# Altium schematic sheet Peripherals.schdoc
size 297 x 209 mm; Symbol: Drawing-Symbol_A4; @Project Name: Hưhwwuey; @Page Count: 2; @Update Date: 2026-10-03; @Create Date: 2026-10-03; @Schematic Name: Schematic1; @Page No: 2; @Page Name: P1; Company: EasyEDA.com; Version: V1.0; Page Size: A4; Device: Drawing-Symbol_A4; @Create Time: 22:16:09; @Update Time: 22:16:09; Border: 1; Width: 1170; Height: 825; Region Start: 1; X Region Count: 6; Y Region Count: 4; Blade Width: 10; Title Block Position: 3; @Board Name: Board1
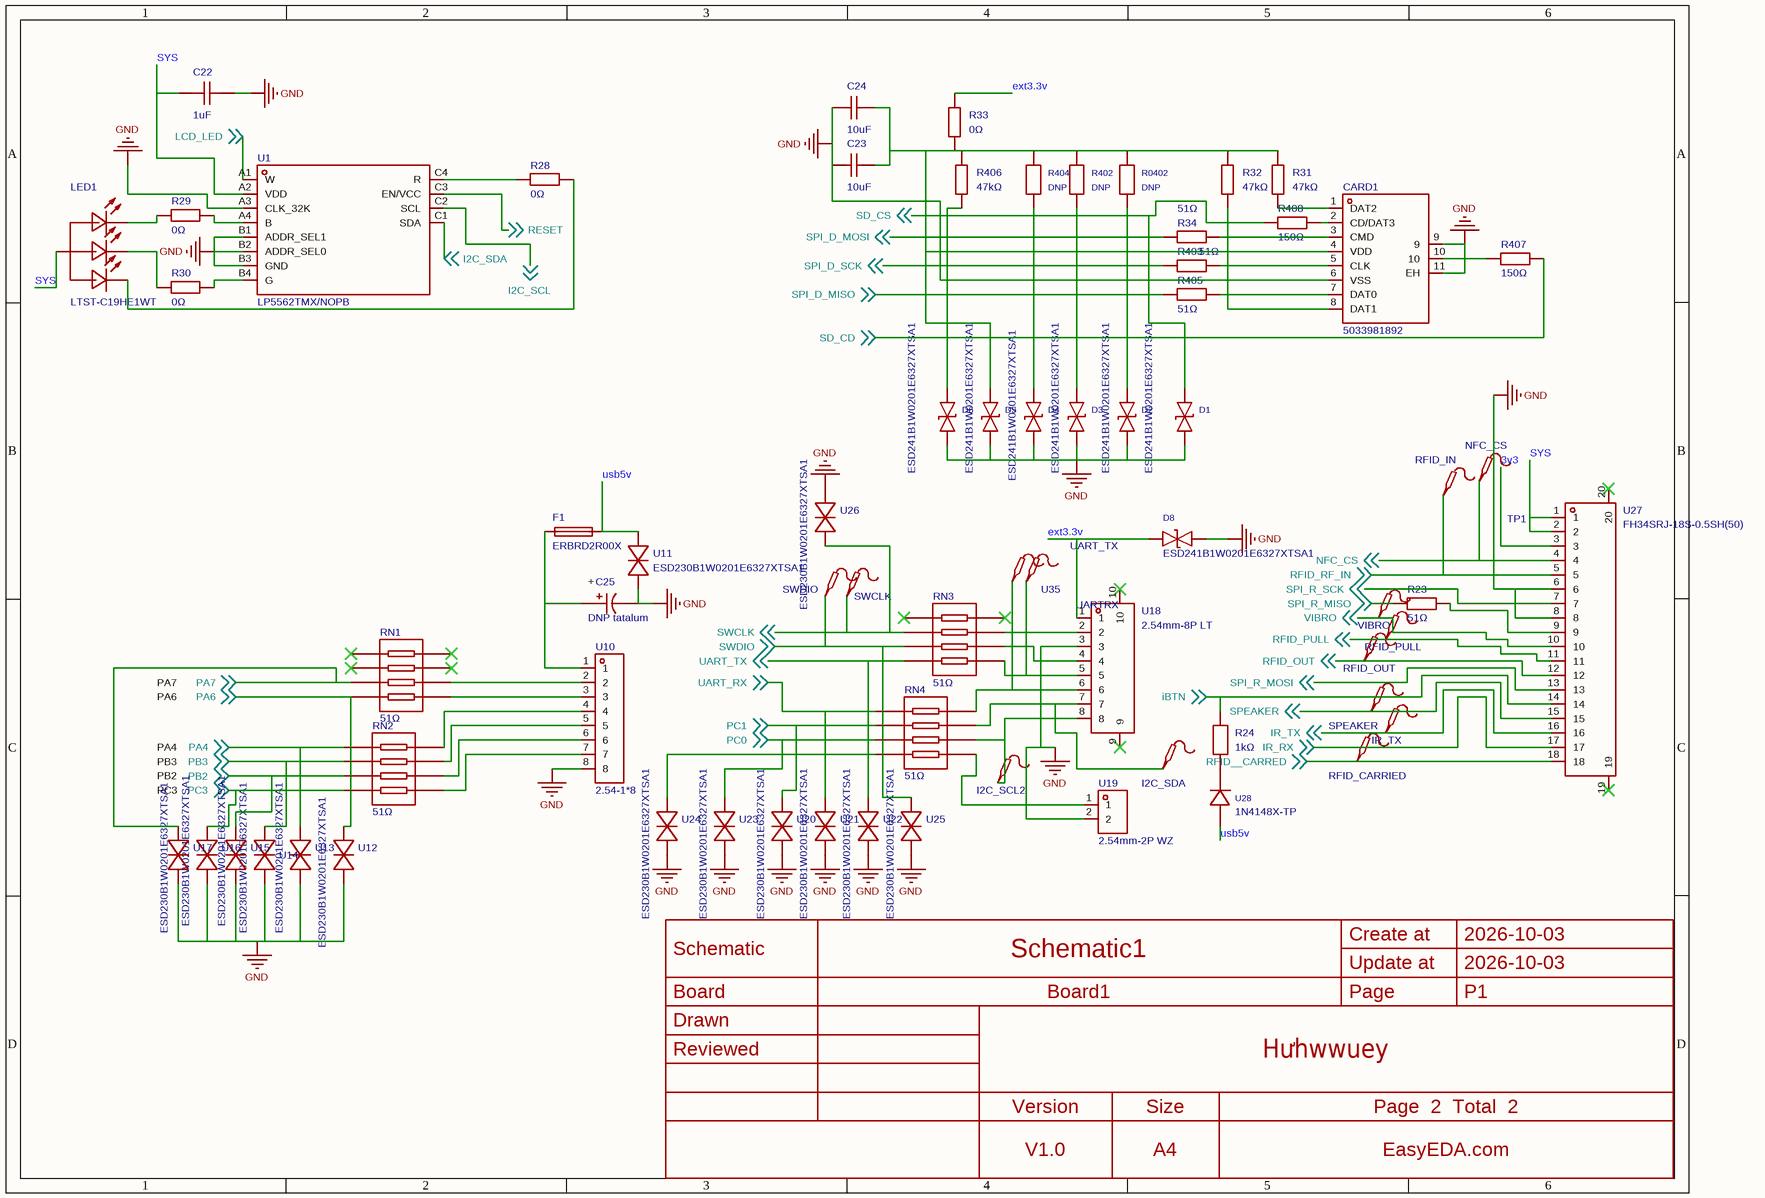
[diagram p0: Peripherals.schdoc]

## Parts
C22  1uF  [C0402]
C23  10uF  [C0603]
C24  10uF  [C0603]
C25  DNP tatalum  [CAP-TH_BD13.0-P5.00-D0.6-FD]
CARD1  5033981892  [TF-SMD_503398-1892]
D1  ESD241B1W0201E6327XTSA1  [WLL-2-3_L0.6-W0.3-P0.36-BI]
D2  ESD241B1W0201E6327XTSA1  [WLL-2-3_L0.6-W0.3-P0.36-BI]
D3  ESD241B1W0201E6327XTSA1  [WLL-2-3_L0.6-W0.3-P0.36-BI]
D4  ESD241B1W0201E6327XTSA1  [WLL-2-3_L0.6-W0.3-P0.36-BI]
D5  ESD241B1W0201E6327XTSA1  [WLL-2-3_L0.6-W0.3-P0.36-BI]
D6  ESD241B1W0201E6327XTSA1  [WLL-2-3_L0.6-W0.3-P0.36-BI]
D8  ESD241B1W0201E6327XTSA1  [WLL-2-3_L0.6-W0.3-P0.36-BI]
F1  ERBRD2R00X  [F0402]
I2C_SCL2  (no value)  [Test-Point-0.5mm]
I2C_SDA  (no value)  [Test-Point-0.5mm]
IR_TX  (no value)  [Test-Point-0.5mm]
LED1  LTST-C19HE1WT  [LED-ARRAY-SMD_4P-L1.6-W1.6-TL-CW]
NFC_CS  (no value)  [Test-Point-0.5mm]
R23  51Ω  [R0402]
R24  1kΩ  [R0402]
R28  0Ω  [R0402]
R29  0Ω  [R0402]
R30  0Ω  [R0402]
R31  47kΩ  [R0402]
R32  47kΩ  [R0402]
R33  0Ω  [R0402]
R34  51Ω  [R0402]
R0402  DNP  [R0402]
R402  DNP  [R0402]
R403  51Ω  [R0402]
R404  DNP  [R0402]
R405  51Ω  [R0402]
R406  47kΩ  [R0402]
R407  150Ω  [R0402]
R408  150Ω  [R0402]
RFID_PULL  (no value)  [Test-Point-0.5mm]
RN1  51Ω  [RES-ARRAY-SMD_0402-8P-L2.0-W1.0-BL]
RN2  51Ω  [RES-ARRAY-SMD_0402-8P-L2.0-W1.0-BL]
RN3  51Ω  [RES-ARRAY-SMD_0402-8P-L2.0-W1.0-BL]
RN4  51Ω  [RES-ARRAY-SMD_0402-8P-L2.0-W1.0-BL]
SWCLK  (no value)  [Test-Point-0.5mm]
SWDIO  (no value)  [Test-Point-0.5mm]
TP1  RFID_IN  [Test-Point-0.5mm]
TP2  RFID_OUT  [Test-Point-0.5mm]
TP3  SPEAKER  [Test-Point-0.5mm]
TP4  RFID_CARRIED  [Test-Point-0.5mm]
U1  LP5562TMX/NOPB  [DSBGA-12_L1.7-W1.3-R3-C4-P0.40-TL]
U10  2.54-1*8  [HDR-TH_8P-P2.54-V-M]
U11  ESD230B1W0201E6327XTSA1  [WLL-2-1_L0.6-W0.3-BI]
U12  ESD230B1W0201E6327XTSA1  [WLL-2-1_L0.6-W0.3-BI]
U13  ESD230B1W0201E6327XTSA1  [WLL-2-1_L0.6-W0.3-BI]
U14  ESD230B1W0201E6327XTSA1  [WLL-2-1_L0.6-W0.3-BI]
U15  ESD230B1W0201E6327XTSA1  [WLL-2-1_L0.6-W0.3-BI]
U16  ESD230B1W0201E6327XTSA1  [WLL-2-1_L0.6-W0.3-BI]
U17  ESD230B1W0201E6327XTSA1  [WLL-2-1_L0.6-W0.3-BI]
U18  2.54mm-8P LT  [CONN-SMD_8P-P2.50_SHOUHAN_2.54MM-8PLT]
U19  2.54mm-2P WZ  [CONN-TH_2P-P2.50_HX-2.54MM-2P-WZ-1]
U20  ESD230B1W0201E6327XTSA1  [WLL-2-1_L0.6-W0.3-BI]
U21  ESD230B1W0201E6327XTSA1  [WLL-2-1_L0.6-W0.3-BI]
U22  ESD230B1W0201E6327XTSA1  [WLL-2-1_L0.6-W0.3-BI]
U23  ESD230B1W0201E6327XTSA1  [WLL-2-1_L0.6-W0.3-BI]
U24  ESD230B1W0201E6327XTSA1  [WLL-2-1_L0.6-W0.3-BI]
U25  ESD230B1W0201E6327XTSA1  [WLL-2-1_L0.6-W0.3-BI]
U26  ESD230B1W0201E6327XTSA1  [WLL-2-1_L0.6-W0.3-BI]
U27  FH34SRJ-18S-0.5SH(50)  [FFC-SMD_18P-P0.50_FH34SRJ-18S-0.5SH]
U28  1N4148X-TP  [SOD-523F_L1.2-W0.8-LS1.7-RD]
U35  UART_TX  [Test-Point-0.5mm]
UARTRX  (no value)  [Test-Point-0.5mm]
VIBRO  (no value)  [Test-Point-0.5mm]

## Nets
GND: C22.2 C23.1 C24.1 C25.2 CARD1.6(VSS) CARD1.9 CARD1.11(EH) D1.1 D2.1 D3.1 D4.1 D5.1 D6.1 D8.1 U1.A3(CLK_32K) U1.B1(ADDR_SEL1) U1.B2(ADDR_SEL0) U1.B3(GND) U10.8 U11.1(C) U12.1(C) U13.1(C) U14.1(C) U15.1(C) U16.1(C) U17.1(C) U18.3 U19.2 U20.1(C) U21.1(C) U22.1(C) U23.1(C) U24.1(C) U25.1(C) U26.2(A) U27.6 U27.8
3v3: U27.3
ext3.3v: D8.2 R33.2 U18.1
I2C_SCL: U1.C2(SCL) ; off-sheet I2C_SCL
I2C_SDA: U1.C1(SDA) ; off-sheet I2C_SDA
iBTN: R24.2 U27.14 ; off-sheet iBTN
IR_RX: U27.17 ; off-sheet IR_RX
IR_TX: IR_TX.1 U27.16 ; off-sheet IR_TX
LCD_LED: U1.A1(W) ; off-sheet LCD_LED
NFC_CS: NFC_CS.1 U27.4 ; off-sheet NFC_CS
PA4: RN2.5 U13.2(A) ; off-sheet PA4
PA6: RN1.8 U12.2(A) ; off-sheet PA6
PA7: RN1.7 U17.2(A) ; off-sheet PA7
PB2: RN2.7 U15.2(A) ; off-sheet PB2
PB3: RN2.6 U14.2(A) ; off-sheet PB3
PC0: RN4.7 U23.2(A) ; off-sheet PC0
PC1: RN4.6 U20.2(A) ; off-sheet PC1
PC3: RN2.8 U16.2(A) ; off-sheet PC3
RESET: U1.C3(EN/VCC) ; off-sheet RESET
RFID__CARRED: TP4.1 U27.18 ; off-sheet RFID__CARRED
RFID_OUT: TP2.1 U27.12 ; off-sheet RFID_OUT
RFID_PULL: RFID_PULL.1 U27.11 ; off-sheet RFID_PULL
RFID_RF_IN: TP1.1 U27.5 ; off-sheet RFID_RF_IN
SD_CD: D6.2 R406.1 R407.2 ; off-sheet SD_CD
SD_CS: D1.2 R408.1 ; off-sheet SD_CS
SPEAKER: TP3.1 U27.15 ; off-sheet SPEAKER
SPI_D_MISO: D4.2 R404.1 R405.1 ; off-sheet SPI_D_MISO
SPI_D_MOSI: D2.2 R34.1 R0402.1 ; off-sheet SPI_D_MOSI
SPI_D_SCK: D3.2 R402.1 R403.1 ; off-sheet SPI_D_SCK
SPI_R_MISO: R23.1 ; off-sheet SPI_R_MISO
SPI_R_MOSI: U27.13 ; off-sheet SPI_R_MOSI
SPI_R_SCK: U27.7 ; off-sheet SPI_R_SCK
SWCLK: RN3.6 SWCLK.1 U26.1(C) ; off-sheet SWCLK
SWDIO: RN3.7 SWDIO.1 U25.2(A) ; off-sheet SWDIO
SYS: C22.1 LED1.4(+) U1.A2(VDD) U27.1 U27.2
UART_RX: RN4.5 U21.2(A) ; off-sheet UART_RX
UART_TX: RN3.8 U22.2(A) ; off-sheet UART_TX
usb5v: F1.2 U11.2(A) U28.2(A)
VIBRO: U27.10 VIBRO.1 ; off-sheet VIBRO
NetC23_2: C23.2 C24.2 CARD1.4(VDD) D5.2 R31.2 R32.2 R33.1 R0402.2 R402.2 R404.2 R406.2
NetC25_1: C25.1 F1.1 U10.1
NetCARD1_1: CARD1.1(DAT2) R31.1
NetCARD1_2: CARD1.2(CD/DAT3) R408.2
NetCARD1_3: CARD1.3(CMD) R34.2
NetCARD1_5: CARD1.5(CLK) R403.2
NetCARD1_7: CARD1.7(DAT0) R405.2
NetCARD1_8: CARD1.8(DAT1) R32.1
NetCARD1_10: CARD1.10 R407.1
NetI2C_SCL2_1: I2C_SCL2.1 RN4.2 U18.8
NetI2C_SDA_1: I2C_SDA.1 RN4.3 U18.7
NetLED1_1: LED1.1(R-) R28.2
NetLED1_2: LED1.2(G-) R30.1
NetLED1_3: LED1.3(B-) R29.1
NetR23_2: R23.2 U27.9
NetR24_1: R24.1 U28.1(C)
NetR28_1: R28.1 U1.C4(R)
NetR29_2: R29.2 U1.A4(B)
NetR30_2: R30.2 U1.B4(G)
NetRN1_1: RN1.1 U10.3
NetRN1_2: RN1.2 U10.2
NetRN2_1: RN2.1 U10.7
NetRN2_2: RN2.2 U10.6
NetRN2_3: RN2.3 U10.5
NetRN2_4: RN2.4 U10.4
NetRN3_1: RN3.1 U18.5 U35.1
NetRN3_2: RN3.2 U18.4
NetRN3_3: RN3.3 U18.2
NetRN4_1: RN4.1 U19.1
NetRN4_4: RN4.4 U18.6 UARTRX.1
NetRN4_8: RN4.8 U24.2(A)

Not connected (* = marked no-connect by the designer): RN1 3* 4* 5* 6*; RN3 4* 5*; U18 9* 10*; U27 19* 20*

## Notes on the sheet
- (near C25) +
- PA7
- PA6
- PA4
- PB3
- PB2
- PC3

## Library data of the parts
C22 = 0402X105K160CT: Capacitance:1uF Tolerance:±10% Tolerance:±10% Voltage Rating:16V Temperature Coefficient:X5R; Manufacturer: Walsin(华新科); AddInBom: yes; ModelId: b7d13df3e9464d7a99d0651d1a5b4d570819f05c4eef4c71ace90d822a990e87; ModelName: C0402_L1.0-W0.5-H0.5; ModelTransform: 39.37,19.685,0,0,0,0,0,0,0; Tolerance: ±10%; Voltage Rating: 16V; Temperature Coefficient: X5R
C23 C24 = 0603X106K160NT: Capacitance:10uF Tolerance:±10% Tolerance:±10% Voltage Rating:16V Temperature Coefficient:X5R; Manufacturer: FH(风华); AddInBom: yes; ModelId: 624118aa3cc7497086c383c2d72e08520819f05c4eef4c71ace90d822a990e87; ModelName: C0603_L1.6-W0.8-H0.8; ModelTransform: 62.992,31.496,0,0,0,0,0,0,0; Tolerance: ±10%; Voltage Rating: 16V; Temperature Coefficient: X5R
C25 = BIPOLAR CAPACITOR 47,0 UF: Manufacturer: Visaton; Add into BOM: no; ConvertToPcb: yes; ModelId: 7c9983bf978a4fc5a02c9caad056438d0819f05c4eef4c71ace90d822a990e87; ModelName: CAP-TH_BD13.0-P5.00-D1.2-FD; ModelTransform: 492.5187,492.025,0,0,0,0,-0.005,0,-137.795
CARD1 = 5033981892: Card Connection Mode:Push-Push Card Type:MicroSD Card (TF Card) Connector Type:Connector and Ejector Additional Card Detection Pins:- Supplementary Features:- Height Above Board:1.28mm Operating Temperature:-25℃~+85℃ Operating Temperature:-25℃~+85℃; Manufacturer: MOLEX; Symbol: 503398-1892; AddInBom: yes; ModelId: b109f9ded9de4b7da3656a36c79492310819f05c4eef4c71ace90d822a990e87; ModelTransform: 515.747,553.149,0,0,0,0,-0.512,25.236,0
D1 D8 = ESD241B1W0201E6327XTSA1: Polarity:Bidirectional Reverse Stand-Off Voltage (Vrwm):3.3V Clamping Voltage:6V Peak Pulse Current (Ipp):4.5A@8/20us Peak Pulse Power Dissipation (Ppp):25W Reverse Leakage Current (Ir):1nA Number of Channels:1 Operating Temperature:-55℃~+125℃ Operating T; Manufacturer: Infineon(英飞凌); 3D Model: cb6ec831a54246eaa6879a507ceff6700819f05c4eef4c71ace90d822a990e87; 3D Model Transform: 22.8346,11.0236,0,0,0,0,0,0,0; Reverse Stand-Off Voltage (Vrwm): 3.3V; Clamping Voltage: 6V; Peak Pulse Power Dissipation (Ppp): 25W; Reverse Leakage Current (Ir): 1nA; Number of Channels: 1; level of protection: IEC 61000-4-4；IEC 61000-4-5；IEC 61000-4-2; Type: TVS; Junction Capacitance: 6.5pF; AddInBom: yes
D2-D6 = ESD241B1W0201E6327XTSA1: Polarity:Bidirectional Reverse Stand-Off Voltage (Vrwm):3.3V Clamping Voltage:6V Peak Pulse Current (Ipp):4.5A@8/20us Peak Pulse Power Dissipation (Ppp):25W Reverse Leakage Current (Ir):1nA Number of Channels:1 Operating Temperature:-55℃~+125℃ Operating T; Manufacturer: Infineon(英飞凌); AddInBom: yes; ModelId: cb6ec831a54246eaa6879a507ceff6700819f05c4eef4c71ace90d822a990e87; ModelTransform: 22.8346,11.0236,0,0,0,0,0,0,0; Reverse Stand-Off Voltage (Vrwm): 3.3V; Clamping Voltage: 6V; Peak Pulse Power Dissipation (Ppp): 25W; Reverse Leakage Current (Ir): 1nA; Number of Channels: 1; level of protection: IEC 61000-4-4；IEC 61000-4-5；IEC 61000-4-2; Type: TVS; Junction Capacitance: 6.5pF
F1 = ERBRD2R00X: Type:Surface Mount Fuse Current Rating:2A Voltage Rating (DC):32V Operating Temperature:-40℃~+125℃ Operating Temperature:-40℃~+125℃ Melting I2t:- Interrupt Rating:35A Diameter (φD):- Length:1mm Width:0.5mm Height:0.39mm Pitch:-; Manufacturer: PANASONIC(松下); AddInBom: yes; ModelId: d1fa61c9223e48b5ae18c323989aa4e50819f05c4eef4c71ace90d822a990e87; ModelTransform: 39.37,20.0787,0,0,0,0,0,0,0; Current Rating: 2A; Voltage Rating (DC): 32V; Interrupt Rating: 35A
I2C_SCL2 I2C_SDA IR_TX NFC_CS RFID_PULL SWCLK SWDIO TP1-TP4 U35 UARTRX VIBRO = Test-Point: Test Point 测试点; AddInBom: yes
LED1 = LTST-C19HE1WT_C458749: Diode Configuration:Common Anode Dominant Wavelength - R:624nm Dominant Wavelength - R:624nm Dominant Wavelength - G:525nm Dominant Wavelength - G:525nm Dominant Wavelength - B:470nm Dominant Wavelength - B:470nm Viewing Angle:130° Lens Color:White Lens A; Manufacturer: LITEON(光宝); AddInBom: yes; ModelId: d6e725dfe50b4987a0e1b2c8fea209e60819f05c4eef4c71ace90d822a990e87; ModelName: LED-ARRAY-SMD_4P-L1.6-W1.6-H0.4-TL-CW; ModelTransform: 62.992,62.992,0,0,0,0,0,0,0; Dominant Wavelength - R: 624nm; Dominant Wavelength - G: 525nm; Dominant Wavelength - B: 470nm; Viewing Angle: 130°; Peak Wavelength - R: 632nm; Peak Wavelength - G: 520nm; Peak Wavelength - B: 468nm; Luminous Intensity - R: 45mcd~180mcd; Luminous Intensity - G: 112mcd~450mcd; Luminous Intensity - B: 28mcd~180mcd; Forward Voltage(Vf) - R: 1.8V~2.4V; Forward Voltage(Vf) - G: 2.8V~3.9V; Forward Current - R: 20mA; Power(Watts) - R: 75mW; Power(Watts) - G: 80mW
R23 = CR0402FF51R0G: Type:Thick Film Resistor Resistance:51Ω Tolerance:±1% Tolerance:±1% Power(Watts):62.5mW Voltage-Supply(Max):50V Temperature Coefficient:±200ppm/℃ Temperature Coefficient:±200ppm/℃ Operating Temperature:-55℃~+125℃ Operating Temperature:-55℃~+125℃; Manufacturer: LIZ(丽智电子); 3D Model: efdecb7dae4442949d28eecaf748420f0819f05c4eef4c71ace90d822a990e87; 3D Model Transform: 39.37,19.685,0,0,0,0,0,0,0; Tolerance: ±1%; Power(Watts): 62.5mW; Voltage-Supply(Max): 50V; AddInBom: yes; ModelName: R0402_L1.0-W0.5-H0.4
R24 = SCR0402F1K: Type:Thick Film Resistor Resistance:1kΩ Tolerance:±1% Tolerance:±1% Power(Watts):62.5mW Voltage-Supply(Max):50V Operating Temperature:-55℃~+155℃ Operating Temperature:-55℃~+155℃; Manufacturer: VO(翔胜); AddInBom: yes; ModelId: efdecb7dae4442949d28eecaf748420f0819f05c4eef4c71ace90d822a990e87; ModelName: R0402_L1.0-W0.5-H0.4; ModelTransform: 39.37,19.685,0,0,0,0,0,0,0; Tolerance: ±1%; Power(Watts): 62.5mW; Voltage-Supply(Max): 50V
R28-R30 R33 = WR04X000PTL: Type:Thick Film Resistor Resistance:0Ω Tolerance:- Tolerance:- Power(Watts):62.5mW Voltage-Supply(Max):50V Temperature Coefficient:-200ppm/℃~+400ppm/℃ Temperature Coefficient:-200ppm/℃~+400ppm/℃ Operating Temperature:-55℃~+155℃ Operating Temperature:-55℃~; Manufacturer: Walsin(华新科); AddInBom: yes; ModelId: efdecb7dae4442949d28eecaf748420f0819f05c4eef4c71ace90d822a990e87; ModelName: R0402_L1.0-W0.5-H0.4; ModelTransform: 39.37,19.685,0,0,0,0,0,0,0; Power(Watts): 62.5mW; Voltage-Supply(Max): 50V
R31 R32 R406 = RC0402JR-0747KL: Type:Thick Film Resistors Resistance: Tolerance:±5% Tolerance:±5% Power(Watts): Overload Voltage (Max): Temperature Coefficient:±100ppm/℃ Temperature Coefficient:±100ppm/℃ Operating Temperature Range:-55℃~+155℃ Operating Temperature Range:-55℃~+155℃; Manufacturer: YAGEO(国巨); AddInBom: yes; ModelId: efdecb7dae4442949d28eecaf748420f0819f05c4eef4c71ace90d822a990e87; ModelName: R0402_L1.0-W0.5-H0.4; ModelTransform: 39.37,19.685,0,0,0,0,0,0,0; Tolerance: ±5%
R34 R403 R405 = CR0402FF51R0G: Type:Thick Film Resistor Resistance:51Ω Tolerance:±1% Tolerance:±1% Power(Watts):62.5mW Voltage-Supply(Max):50V Temperature Coefficient:±200ppm/℃ Temperature Coefficient:±200ppm/℃ Operating Temperature:-55℃~+125℃ Operating Temperature:-55℃~+125℃; Manufacturer: LIZ(丽智电子); AddInBom: yes; ModelId: efdecb7dae4442949d28eecaf748420f0819f05c4eef4c71ace90d822a990e87; ModelName: R0402_L1.0-W0.5-H0.4; ModelTransform: 39.37,19.685,0,0,0,0,0,0,0; Tolerance: ±1%; Power(Watts): 62.5mW; Voltage-Supply(Max): 50V
R0402 R402 R404 = SCR0402F6R04: Type:Thick Film Resistor Resistance:6.04Ω Tolerance:±1% Tolerance:±1% Power(Watts):62.5mW Voltage-Supply(Max):50V Temperature Coefficient:±400ppm/℃ Temperature Coefficient:±400ppm/℃ Operating Temperature:-55℃~+155℃ Operating Temperature:-55℃~+155℃; Manufacturer: VO(翔胜); Add into BOM: no; ConvertToPcb: yes; ModelId: efdecb7dae4442949d28eecaf748420f0819f05c4eef4c71ace90d822a990e87; ModelName: R0402_L1.0-W0.5-H0.4; ModelTransform: 39.37,19.685,0,0,0,0,0,0,0; Tolerance: ±1%; Power(Watts): 62.5mW; Voltage-Supply(Max): 50V
R407 R408 = RC0402JR-07150RL: Type:Thick Film Resistor Resistance:150Ω Tolerance:±5% Tolerance:±5% Power(Watts):62.5mW Voltage-Supply(Max):50V Temperature Coefficient:±100ppm/℃ Temperature Coefficient:±100ppm/℃ Operating Temperature:-55℃~+155℃ Operating Temperature:-55℃~+155℃; Manufacturer: YAGEO(国巨); AddInBom: yes; ModelId: efdecb7dae4442949d28eecaf748420f0819f05c4eef4c71ace90d822a990e87; ModelName: R0402_L1.0-W0.5-H0.4; ModelTransform: 39.37,19.685,0,0,0,0,0,0,0; Tolerance: ±5%; Power(Watts): 62.5mW; Voltage-Supply(Max): 50V
RN1-RN4 = WA04X510JTL: Number of Resistors: Resistance:51Ω Tolerance:±5% Tolerance:±5% Power(Watts):62.5mW Temperature Coefficient:±200ppm/℃ Temperature Coefficient:±200ppm/℃ Number of Pins:; Manufacturer: Walsin(华新科); AddInBom: yes; ModelId: b65ad64283804470aa890dd9c23ebfa10819f05c4eef4c71ace90d822a990e87; ModelName: R0402-8P_L2.0-W1.0-H0.5; ModelTransform: 78.74,39.37,0,180,0,0,-0.001,-0.001,0; Tolerance: ±5%; Power(Watts): 62.5mW
U1 = LP5562TMX/NOPB: Type:- Voltage - Input(DC):2.7V~5.5V Voltage - Input(DC):2.7V~5.5V Frequency - Switching:558Hz；256Hz Frequency - Switching:558Hz；256Hz Number of Channels:4 Output Current:25.5mA Dimming:I2C Features:Over-Temperature Protection (OTP) Operating temperature:; Manufacturer: TI(德州仪器); AddInBom: yes; ModelId: fc7c6e7f91ed4f8196740629c16730090819f05c4eef4c71ace90d822a990e87; ModelTransform: 66.929,51.181,0,0,0,0,0,0,0; Number of Channels: 4; Output Current: 25.5mA; Dimming: I2C; Constant Current Accuracy: 5%
U10 = 2.54-1*8: Pin Structure:1x8P Pitch:2.54mm Circluar Pins/Square Pins:Pin Header Mounting Type:Through Hole Number of Rows:1 Number of Pins:8P Current Rating:2.5A Length of Mating Pin:6mm Insulation Height:2.54mm Length of End Connection Pin:3mm Contact Material:Bras; Manufacturer: ZHOURI(洲日); Add into BOM: yes; 3D Model: 926dcf5c05be473f8295f20cc8ccf72f; 3D Model Transform: 807.87244,98.425,0,0,0,0,0,0,-118.11; Pin Structure: 1x8P; Pitch: 2.54mm; Current Rating: 2.5A
U11-U17 U20-U26 = ESD230B1W0201E6327XTSA1: Reverse Stand-Off Voltage (Vrwm):5.5V Clamping Voltage:15V Peak Pulse Current (Ipp):3A@8/20us Peak Pulse Power Dissipation (Ppp):56W Voltage - Breakdown:6.05V Reverse Leakage Current (Ir):1nA Operating Temperature:-55℃~+125℃ Operating Temperature:-55℃~+12; Manufacturer: Infineon(英飞凌); AddInBom: yes; ModelId: e9ba6bad375e4bb7980be781c89bfdc60819f05c4eef4c71ace90d822a990e87; ModelTransform: 22.8346,11.0236,0,0,0,0,0,0,0; Reverse Stand-Off Voltage (Vrwm): 5.5V; Clamping Voltage: 15V; Peak Pulse Power Dissipation (Ppp): 56W; Voltage - Breakdown: 6.05V; Reverse Leakage Current (Ir): 1nA; level of protection: IEC 61000-4-4；IEC 61000-4-5；IEC 61000-4-2; Junction Capacitance: 7pF
U18 = 2.54mm-8P LT: Pins Structure:1x8P Pitch:2.54mm Mounting Type:Surface Mount,Vertical Reference Series:XH Number of Pins:8P Number of Rows:1 Number of PINs Per Row:8 Row Spacing:- Current Rating:3A Contact Material:Brass Contact Plating:Tin Operating Temperature:-25℃~+85; Manufacturer: SHOU HAN(首韩); Add into BOM: yes; Pins Structure: 1x8P; Pitch: 2.54mm; Reference Series: XH; Number of PINs Per Row: 8; Current Rating: 3A; Voltage Rating: 250V; Plastic Material: LCP; Flame Retardant Rating: UL94V-0
U19 = 2.54mm-2P WZ: Pins Structure:1x2P Pitch:2.54mm Mounting Type:Right Angle Reference Series:XH Number of Pins:2P Number of Rows:1 Number of PINs Per Row:2 Row Spacing:- Current Rating:3A Contact Material:Brass Contact Plating:Tin Operating Temperature:-25℃~+85℃ Operating; Manufacturer: SHOU HAN(首韩); Add into BOM: yes; 3D Model: b2f95090ff9941b1b83cd3f8173352e2; 3D Model Transform: 295.669,299.212,0,0,0,0,-0.79,-132.795,-137.795; Pins Structure: 1x2P; Pitch: 2.54mm; Reference Series: XH; Number of PINs Per Row: 2; Current Rating: 3A; Voltage Rating: 250V; Plastic Material: PA66; Flame Retardant Rating: UL94V-0
U27 = FH34SRJ-18S-0.5SH(50): Locking Feature:Flip-top (front insert,rear flip) Contact Type:Double-Sided Contacts, Top and Bottom Entry Number of Contacts:18P Pitch:0.5mm Mounting Type:Surface Mount, Right Angle FFC, FCB Thickness:0.3mm FFC, FCB Thickness:0.3mm Height Above Board:1mm; Manufacturer: HRS(广濑); Add into BOM: yes; 3D Model: ebf172207cb640f5a031a3b119151af9; 3D Model Transform: 433.464,149.606,0,0,0,0,0,5.551,0; Number of Contacts: 18P; Pitch: 0.5mm; FFC, FCB Thickness: 0.3mm; Rated Voltage (Max): 50V; Current Rating (Max): 500mA; FPC/FFC Lock: Without buckle; Forward Foot / Back Foot: No polarity
U28 = 1N4148X-TP: Diode Configuration:1 Independent Pd - Power Dissipation:200mW Current - Rectified:150mA Voltage - DC Reverse(Vr):75V Voltage - Forward(Vf@If):1.25V@150mA Non-Repetitive Peak Forward Surge Current:2A Reverse Leakage Current (Ir):1uA@75V Reverse Recovery T; Manufacturer: MCC(美微科); AddInBom: yes; ModelId: 53f385f253c24b16903baed56d7fb4c80819f05c4eef4c71ace90d822a990e87; ModelName: SOD-523F_L1.2-W0.8-H0.6-LS1.6; ModelTransform: 62.992,31.496,0,0,0,0,-0.005,0.16,0; Pd - Power Dissipation: 200mW; Current - Rectified: 150mA; Voltage - DC Reverse(Vr): 75V; Non-Repetitive Peak Forward Surge Current: 2A; Reverse Recovery Time (trr): 4ns; Operating Junction Temperature Range: -65℃~+150℃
